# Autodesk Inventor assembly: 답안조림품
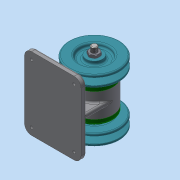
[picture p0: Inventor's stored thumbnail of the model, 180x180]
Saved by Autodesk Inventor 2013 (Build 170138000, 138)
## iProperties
Created: 2019-09
Part Number: 답안조림품
Document SubType Name: Assembly
Designer: Administrator
Author: Administrator
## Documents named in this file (10)
- C:\Users\Administrator\Desktop\490904V1021\답안조림품.iam
- C:\Users\Administrator\Desktop\490904V1021\본체.ipt
- C:\Users\Administrator\Desktop\490904V1021\V-벨트풀리.ipt
- C:\Users\Administrator\Desktop\490904V1021\너트 M10x1.ipt
- C:\Users\Administrator\Desktop\490904V1021\베어링 6004.ipt
- C:\Users\Administrator\Desktop\490904V1021\볼트 M4.ipt
- C:\Users\Administrator\Desktop\490904V1021\오일 실 17 30 5.ipt
- C:\Users\Administrator\Desktop\490904V1021\축.ipt
- C:\Users\Administrator\Desktop\490904V1021\커버.ipt
- C:\Users\Administrator\Desktop\490904V1021\키 5 x 5 x 12.ipt
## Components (2 placed, 1 different names)
1. V-벨트풀리:1
2. V-벨트풀리:2
